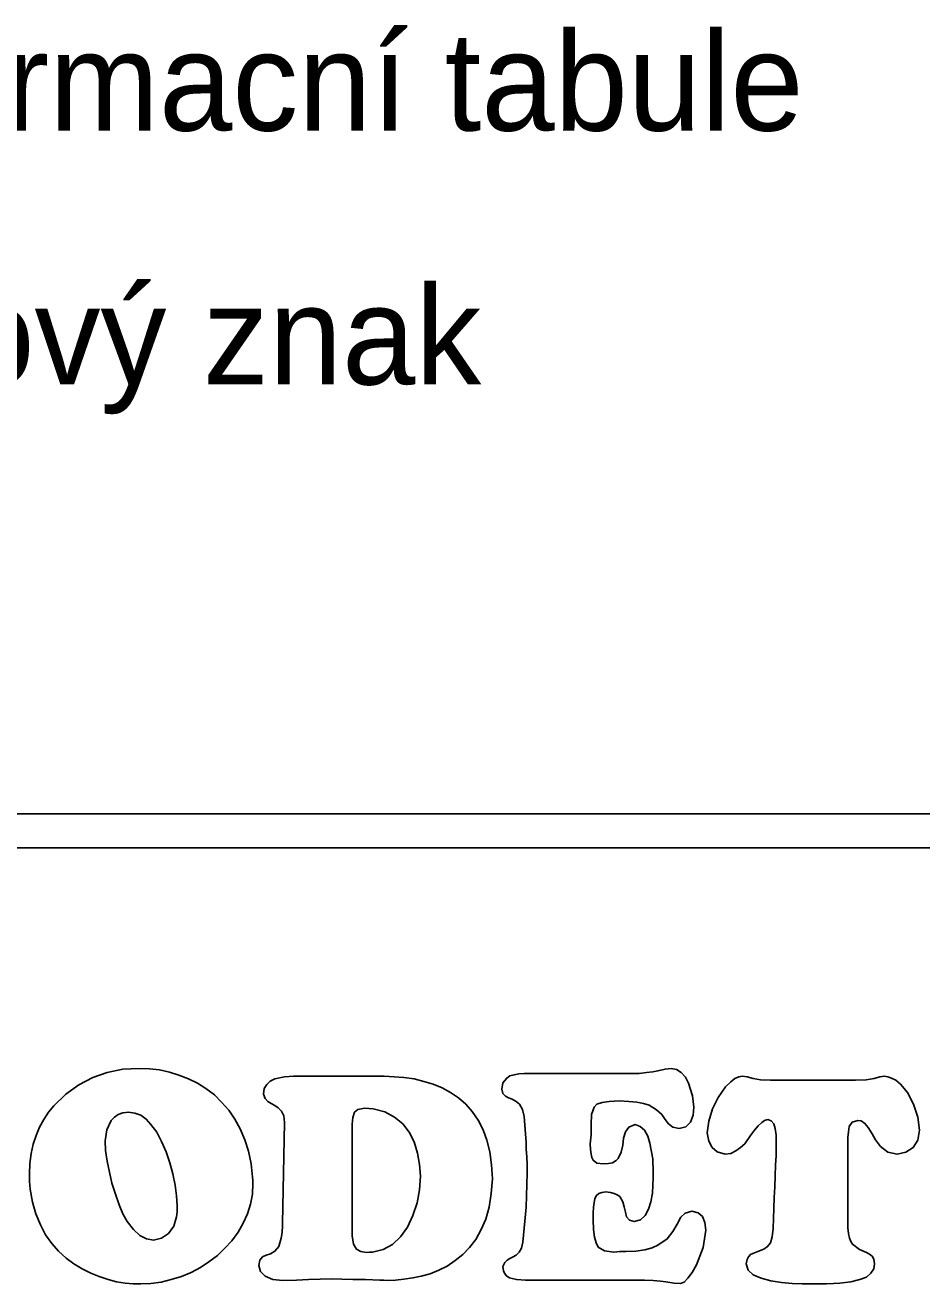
# Model space of a CAD drawing. Extents: x -866693 to -866303, y -1041966 to -1040244.
# Drawn here: x -866384.41 to -866375.66, y -1041631.07 to -1041618.79 of the extents above; entities that cross this region are included whole.
import ezdxf

# ---------------------------------------------------------------- set-up
doc = ezdxf.new("R2010")
doc.units = 0
doc.layers.add('Legenda', color=7, linetype='Continuous')
doc.layers.add('Tabulka', color=7, linetype='Continuous')

msp = doc.modelspace()

# ---------------------------------------------------------------- linework, layer by layer
at = {"layer": 'Tabulka'}
for p, q in [((-866366.718, -1041626.488), (-866404.081, -1041626.488)), ((-866404.081, -1041626.818), (-866366.718, -1041626.818))]:
    msp.add_line(p, q, dxfattribs=at)
for points in [[(-866384.357, -1041630.146), (-866384.336, -1041630.274), (-866384.303, -1041630.389), (-866384.257, -1041630.497), (-866384.208, -1041630.592), (-866384.146, -1041630.679), (-866384.08, -1041630.753), (-866384.006, -1041630.819), (-866383.931, -1041630.877), (-866383.849, -1041630.926), (-866383.766, -1041630.968), (-866383.683, -1041631.001), (-866383.597, -1041631.03), (-866383.514, -1041631.05), (-866383.431, -1041631.063), (-866383.353, -1041631.071), (-866383.279, -1041631.071), (-866383.18, -1041631.067), (-866383.08, -1041631.054), (-866382.981, -1041631.03), (-866382.882, -1041631.001), (-866382.787, -1041630.959), (-866382.696, -1041630.91), (-866382.614, -1041630.856), (-866382.531, -1041630.794), (-866382.457, -1041630.724), (-866382.391, -1041630.65), (-866382.329, -1041630.567), (-866382.279, -1041630.48), (-866382.238, -1041630.389), (-866382.209, -1041630.294), (-866382.188, -1041630.195), (-866382.184, -1041630.088), (-866382.184, -1041630.059), (-866382.188, -1041630.03), (-866382.201, -1041629.902), (-866382.226, -1041629.778), (-866382.263, -1041629.667), (-866382.308, -1041629.559), (-866382.362, -1041629.464), (-866382.42, -1041629.378), (-866382.49, -1041629.299), (-866382.56, -1041629.229), (-866382.643, -1041629.167), (-866382.725, -1041629.113), (-866382.812, -1041629.072), (-866382.907, -1041629.035), (-866382.998, -1041629.006), (-866383.097, -1041628.985), (-866383.192, -1041628.973), (-866383.291, -1041628.969), (-866383.452, -1041628.977), (-866383.605, -1041629.01), (-866383.745, -1041629.06), (-866383.882, -1041629.13), (-866384.01, -1041629.221), (-866384.125, -1041629.336), (-866384.179, -1041629.398), (-866384.224, -1041629.469), (-866384.266, -1041629.543), (-866384.299, -1041629.625), (-866384.328, -1041629.708), (-866384.348, -1041629.799), (-866384.361, -1041629.898), (-866384.365, -1041629.997), (-866384.365, -1041630.071)], [(-866381.875, -1041629.497), (-866381.895, -1041630.484), (-866381.895, -1041630.489), (-866381.895, -1041630.501), (-866381.899, -1041630.571), (-866381.908, -1041630.625), (-866381.92, -1041630.67), (-866381.932, -1041630.707), (-866381.97, -1041630.753), (-866382.011, -1041630.778), (-866382.056, -1041630.79), (-866382.089, -1041630.807), (-866382.118, -1041630.84), (-866382.127, -1041630.893), (-866382.11, -1041630.951), (-866382.065, -1041630.997), (-866381.99, -1041631.03), (-866381.891, -1041631.038), (-866381.759, -1041631.034), (-866381.643, -1041631.03), (-866381.528, -1041631.025), (-866381.412, -1041631.021), (-866381.317, -1041631.025), (-866381.21, -1041631.03), (-866381.086, -1041631.03), (-866380.945, -1041631.034), (-866380.908, -1041631.034), (-866380.871, -1041631.038), (-866380.793, -1041631.034), (-866380.71, -1041631.025), (-866380.623, -1041631.013), (-866380.541, -1041630.997), (-866380.454, -1041630.972), (-866380.371, -1041630.939), (-866380.289, -1041630.897), (-866380.21, -1041630.844), (-866380.136, -1041630.786), (-866380.07, -1041630.716), (-866380.008, -1041630.637), (-866379.958, -1041630.542), (-866379.913, -1041630.439), (-866379.88, -1041630.323), (-866379.859, -1041630.191), (-866379.847, -1041630.047), (-866379.855, -1041629.91), (-866379.872, -1041629.782), (-866379.901, -1041629.671), (-866379.938, -1041629.568), (-866379.987, -1041629.473), (-866380.045, -1041629.39), (-866380.107, -1041629.32), (-866380.177, -1041629.258), (-866380.256, -1041629.204), (-866380.338, -1041629.159), (-866380.425, -1041629.122), (-866380.516, -1041629.097), (-866380.611, -1041629.072), (-866380.71, -1041629.06), (-866380.805, -1041629.051), (-866380.904, -1041629.047), (-866381.755, -1041629.047), (-866381.767, -1041629.047), (-866381.788, -1041629.047), (-866381.875, -1041629.051), (-866381.97, -1041629.072), (-866382.015, -1041629.093), (-866382.048, -1041629.126), (-866382.073, -1041629.167), (-866382.081, -1041629.221), (-866382.065, -1041629.262), (-866382.04, -1041629.291), (-866382.007, -1041629.312), (-866381.97, -1041629.332), (-866381.937, -1041629.353), (-866381.904, -1041629.386), (-866381.883, -1041629.431)], [(-866382.928, -1041630.418), (-866382.957, -1041630.509), (-866383.006, -1041630.579), (-866383.076, -1041630.625), (-866383.155, -1041630.645), (-866383.221, -1041630.633), (-866383.287, -1041630.6), (-866383.349, -1041630.542), (-866383.411, -1041630.464), (-866383.452, -1041630.389), (-866383.489, -1041630.299), (-866383.526, -1041630.195), (-866383.559, -1041630.088), (-866383.584, -1041629.981), (-866383.605, -1041629.873), (-866383.621, -1041629.77), (-866383.626, -1041629.675), (-866383.609, -1041629.568), (-866383.568, -1041629.477), (-866383.535, -1041629.444), (-866383.498, -1041629.419), (-866383.452, -1041629.402), (-866383.398, -1041629.398), (-866383.336, -1041629.407), (-866383.279, -1041629.427), (-866383.225, -1041629.464), (-866383.18, -1041629.518), (-866383.122, -1041629.592), (-866383.076, -1041629.683), (-866383.031, -1041629.782), (-866382.994, -1041629.89), (-866382.965, -1041629.997), (-866382.944, -1041630.109), (-866382.928, -1041630.212), (-866382.924, -1041630.311), (-866382.924, -1041630.369)], [(-866381.012, -1041629.365), (-866380.896, -1041629.394), (-866380.801, -1041629.444), (-866380.722, -1041629.51), (-866380.66, -1041629.592), (-866380.611, -1041629.687), (-866380.578, -1041629.795), (-866380.557, -1041629.906), (-866380.549, -1041630.022), (-866380.557, -1041630.154), (-866380.582, -1041630.282), (-866380.623, -1041630.406), (-866380.677, -1041630.517), (-866380.743, -1041630.612), (-866380.822, -1041630.687), (-866380.912, -1041630.736), (-866381.016, -1041630.761), (-866381.045, -1041630.761), (-866381.078, -1041630.765), (-866381.131, -1041630.757), (-866381.173, -1041630.732), (-866381.201, -1041630.683), (-866381.214, -1041630.604), (-866381.214, -1041629.514), (-866381.21, -1041629.448), (-866381.193, -1041629.398), (-866381.16, -1041629.369), (-866381.094, -1041629.357), (-866381.053, -1041629.361)]]:
    msp.add_lwpolyline(points, close=True, dxfattribs=at)
for points in [[(-866378.889, -1041629.762), (-866378.893, -1041629.704), (-866378.885, -1041629.617), (-866378.885, -1041629.518), (-866378.881, -1041629.419), (-866378.856, -1041629.349), (-866378.827, -1041629.32), (-866378.777, -1041629.303), (-866378.707, -1041629.291), (-866378.612, -1041629.287), (-866378.517, -1041629.291), (-866378.439, -1041629.299), (-866378.373, -1041629.312), (-866378.319, -1041629.328), (-866378.245, -1041629.374), (-866378.195, -1041629.419), (-866378.162, -1041629.469), (-866378.129, -1041629.51), (-866378.088, -1041629.543), (-866378.026, -1041629.555), (-866377.96, -1041629.539), (-866377.914, -1041629.493), (-866377.889, -1041629.427), (-866377.881, -1041629.349), (-866377.894, -1041629.237), (-866377.935, -1041629.113), (-866377.964, -1041629.056), (-866378.005, -1041629.01), (-866378.051, -1041628.981), (-866378.104, -1041628.969), (-866378.162, -1041628.977), (-866378.232, -1041628.994), (-866378.282, -1041629.002), (-866378.344, -1041629.01), (-866378.414, -1041629.018), (-866378.501, -1041629.018), (-866378.629, -1041629.018), (-866378.757, -1041629.018), (-866378.893, -1041629.018), (-866379.025, -1041629.018), (-866379.157, -1041629.018), (-866379.285, -1041629.018), (-866379.413, -1041629.018), (-866379.537, -1041629.018), (-866379.591, -1041629.023), (-866379.636, -1041629.031), (-866379.678, -1041629.043), (-866379.707, -1041629.064), (-866379.744, -1041629.109), (-866379.756, -1041629.171), (-866379.744, -1041629.213), (-866379.719, -1041629.241), (-866379.69, -1041629.258), (-866379.653, -1041629.27), (-866379.616, -1041629.291), (-866379.583, -1041629.32), (-866379.554, -1041629.369), (-866379.537, -1041629.44), (-866379.529, -1041629.564), (-866379.517, -1041629.692), (-866379.517, -1041629.758), (-866379.512, -1041629.832), (-866379.508, -1041629.906), (-866379.508, -1041629.993)], [(-866376.378, -1041630.109), (-866376.378, -1041629.642), (-866376.374, -1041629.588), (-866376.366, -1041629.535), (-866376.337, -1041629.493), (-866376.283, -1041629.477), (-866376.25, -1041629.481), (-866376.213, -1041629.506), (-866376.18, -1041629.547), (-866376.143, -1041629.609), (-866376.11, -1041629.667), (-866376.06, -1041629.733), (-866375.99, -1041629.787), (-866375.899, -1041629.807), (-866375.812, -1041629.787), (-866375.742, -1041629.741), (-866375.697, -1041629.671), (-866375.68, -1041629.572), (-866375.697, -1041629.444), (-866375.738, -1041629.32), (-866375.796, -1041629.204), (-866375.866, -1041629.122), (-866375.911, -1041629.084), (-866375.953, -1041629.064), (-866375.99, -1041629.051), (-866376.023, -1041629.047), (-866376.068, -1041629.051), (-866376.122, -1041629.068), (-866376.2, -1041629.08), (-866376.304, -1041629.084), (-866377.134, -1041629.084), (-866377.233, -1041629.08), (-866377.303, -1041629.068), (-866377.361, -1041629.051), (-866377.41, -1041629.047), (-866377.443, -1041629.051), (-866377.481, -1041629.068), (-866377.522, -1041629.101), (-866377.572, -1041629.151), (-866377.646, -1041629.254), (-866377.7, -1041629.365), (-866377.737, -1041629.485), (-866377.753, -1041629.597), (-866377.737, -1041629.679), (-866377.704, -1041629.741), (-866377.654, -1041629.782), (-866377.576, -1041629.807), (-866377.522, -1041629.799), (-866377.472, -1041629.774), (-866377.427, -1041629.741), (-866377.386, -1041629.704), (-866377.328, -1041629.625), (-866377.291, -1041629.572), (-866377.254, -1041629.53), (-866377.22, -1041629.497), (-866377.192, -1041629.477), (-866377.159, -1041629.469), (-866377.126, -1041629.481), (-866377.101, -1041629.51), (-866377.088, -1041629.555), (-866377.08, -1041629.621), (-866377.08, -1041629.671), (-866377.08, -1041629.737), (-866377.08, -1041629.82), (-866377.084, -1041629.915), (-866377.088, -1041630.018), (-866377.092, -1041630.125), (-866377.097, -1041630.228), (-866377.101, -1041630.336), (-866377.105, -1041630.435), (-866377.109, -1041630.53), (-866377.117, -1041630.612), (-866377.134, -1041630.67), (-866377.163, -1041630.707), (-866377.2, -1041630.732), (-866377.258, -1041630.757), (-866377.307, -1041630.774), (-866377.328, -1041630.786), (-866377.349, -1041630.807), (-866377.361, -1041630.835), (-866377.373, -1041630.877), (-866377.353, -1041630.939), (-866377.303, -1041630.984), (-866377.225, -1041631.017), (-866377.13, -1041631.042), (-866377.026, -1041631.058), (-866376.923, -1041631.067), (-866376.824, -1041631.071), (-866376.741, -1041631.071), (-866376.663, -1041631.071), (-866376.589, -1041631.071), (-866376.518, -1041631.067), (-866376.457, -1041631.063), (-866376.349, -1041631.05), (-866376.262, -1041631.03), (-866376.196, -1041631.005), (-866376.155, -1041630.968), (-866376.126, -1041630.926), (-866376.118, -1041630.877), (-866376.126, -1041630.831), (-866376.143, -1041630.802)], [(-866379.508, -1041629.993), (-866379.517, -1041630.323), (-866379.55, -1041630.666), (-866379.562, -1041630.724), (-866379.587, -1041630.761), (-866379.616, -1041630.79), (-866379.645, -1041630.807), (-866379.678, -1041630.823), (-866379.702, -1041630.84), (-866379.727, -1041630.864), (-866379.744, -1041630.902), (-866379.74, -1041630.943), (-866379.727, -1041630.972), (-866379.707, -1041630.997), (-866379.682, -1041631.013), (-866379.612, -1041631.03), (-866379.525, -1041631.034), (-866379.492, -1041631.034), (-866379.467, -1041631.034), (-866378.48, -1041631.034), (-866378.364, -1041631.034), (-866378.278, -1041631.038), (-866378.207, -1041631.046), (-866378.154, -1041631.05), (-866378.075, -1041631.063), (-866378.013, -1041631.067), (-866377.976, -1041631.054), (-866377.939, -1041631.017), (-866377.898, -1041630.959), (-866377.856, -1041630.885), (-866377.79, -1041630.716), (-866377.766, -1041630.546), (-866377.774, -1041630.472), (-866377.799, -1041630.414), (-866377.84, -1041630.377), (-866377.902, -1041630.361), (-866377.968, -1041630.381), (-866378.009, -1041630.422), (-866378.046, -1041630.489), (-866378.088, -1041630.559), (-866378.141, -1041630.633), (-866378.232, -1041630.695), (-866378.29, -1041630.72), (-866378.36, -1041630.74), (-866378.447, -1041630.753), (-866378.546, -1041630.757), (-866378.604, -1041630.757), (-866378.662, -1041630.761), (-866378.753, -1041630.749), (-866378.815, -1041630.712), (-866378.835, -1041630.67), (-866378.852, -1041630.617), (-866378.86, -1041630.542), (-866378.864, -1041630.447), (-866378.864, -1041630.381), (-866378.86, -1041630.323), (-866378.856, -1041630.278), (-866378.848, -1041630.241), (-866378.835, -1041630.212), (-866378.81, -1041630.191), (-866378.781, -1041630.179), (-866378.74, -1041630.175), (-866378.695, -1041630.179), (-866378.658, -1041630.191), (-866378.629, -1041630.204), (-866378.604, -1041630.22), (-866378.575, -1041630.27), (-866378.563, -1041630.319), (-866378.55, -1041630.373), (-866378.538, -1041630.418), (-866378.509, -1041630.451), (-866378.464, -1041630.464), (-866378.402, -1041630.447), (-866378.356, -1041630.406), (-866378.323, -1041630.344), (-866378.302, -1041630.27), (-866378.286, -1041630.187), (-866378.282, -1041630.109), (-866378.278, -1041630.038), (-866378.278, -1041629.985), (-866378.282, -1041629.853), (-866378.311, -1041629.7), (-866378.331, -1041629.63), (-866378.364, -1041629.572), (-866378.406, -1041629.535), (-866378.455, -1041629.518), (-866378.517, -1041629.543), (-866378.55, -1041629.588), (-866378.567, -1041629.65), (-866378.575, -1041629.72), (-866378.592, -1041629.787), (-866378.62, -1041629.848), (-866378.641, -1041629.869), (-866378.674, -1041629.89), (-866378.715, -1041629.898), (-866378.765, -1041629.902), (-866378.827, -1041629.894), (-866378.864, -1041629.865), (-866378.876, -1041629.84), (-866378.885, -1041629.807), (-866378.889, -1041629.762)], [(-866376.143, -1041630.802), (-866376.167, -1041630.782), (-866376.196, -1041630.765), (-866376.267, -1041630.736), (-866376.333, -1041630.683), (-866376.349, -1041630.658), (-866376.362, -1041630.625), (-866376.374, -1041630.579), (-866376.378, -1041630.526), (-866376.378, -1041630.109)]]:
    msp.add_lwpolyline(points, dxfattribs=at)

# ---------------------------------------------------------------- texts
at = {"layer": 'Legenda'}
for s, p in [('informacní tabule', (-866386.672, -1041619.823)), ('tycový znak', (-866386.672, -1041622.299))]:
    msp.add_text(s, height=0.9614, dxfattribs=at).set_placement(p)

doc.saveas('drawing.dxf')
